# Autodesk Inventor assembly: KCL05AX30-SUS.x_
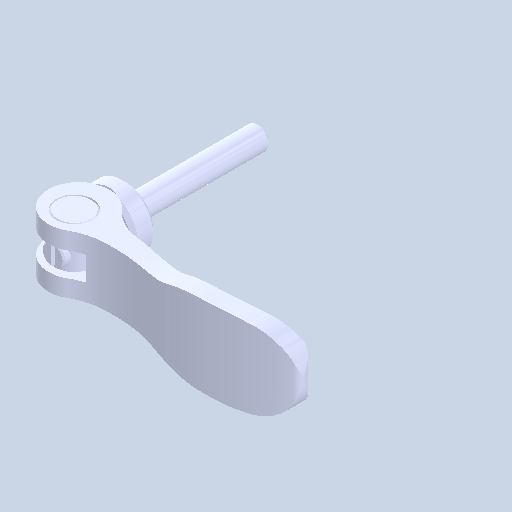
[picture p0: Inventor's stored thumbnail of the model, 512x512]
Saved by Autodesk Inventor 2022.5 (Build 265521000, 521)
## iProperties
Created: 2024-08
Part Number: KCL05AX30-SUS.x_
Document SubType Name: Assembly
Designer: ImaoCorp
Author: ImaoCorp
Sending System: SOLIDWORKS 2022-2022290
MC: AMD64
MC_MODEL: Intel64 Family 6 Model 60 Stepping 3, GenuineIntel
OS: Windows_NT
FRU: Parasolid Version 33.1, build 260,  4-25-2022
FORMAT: text
GUISE: transmit
KEY: FILEKCL05AX30-SUS.x_t
DATE: Thu Aug 29 10:48:37 2024
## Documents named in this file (5)
- Y:\5.更新分\2024年対応\1001_KCL\データ\kcl05ax30-sus\KCL05AX30-SUS.x_.iam
- Y:\5.更新分\2024年対応\1001_KCL\データ\kcl05ax30-sus\KCL05AX30-SUS_01.ipt
- Y:\5.更新分\2024年対応\1001_KCL\データ\kcl05ax30-sus\KCL05AX30-SUS_02.ipt
- Y:\5.更新分\2024年対応\1001_KCL\データ\kcl05ax30-sus\KCL05AX30-SUS_03.ipt
- Y:\5.更新分\2024年対応\1001_KCL\データ\kcl05ax30-sus\KCL05AX30-SUS_04.ipt
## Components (4 placed, 4 different names)
1. KCL05AX30-SUS_01
2. KCL05AX30-SUS_02
3. KCL05AX30-SUS_03
4. KCL05AX30-SUS_04
